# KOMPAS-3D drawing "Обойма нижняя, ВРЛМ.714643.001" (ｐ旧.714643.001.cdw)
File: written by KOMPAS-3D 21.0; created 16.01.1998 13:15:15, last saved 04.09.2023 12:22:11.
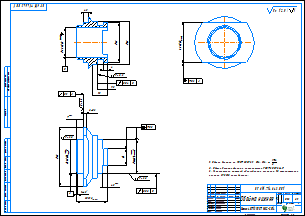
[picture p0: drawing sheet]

Sheet 1: A2, landscape

Document properties: Масса: 0.13304; Литера: О@111~; Знак неуказанной шероховатости: 4; Параметр неуказанной шероховатости: Ra 12,5; Полное имя файла: D:\2023\Чертежи dwg cdw\ВРЛМ.714643.001_.cdw

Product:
- Part/product: Обойма нижняя  | designation ВРЛМ.714643.001
    Материал: Сталь 40Х13 ГОСТ 5632-2014 (density 7650 kg/m3)
    Масса: 0.13304

Title block, sheet 1: Наименование: Обойма нижняя; designation: ВРЛМ.714643.001; Материал: Сталь 40Х13 ГОСТ 5632-2014; Масса: 0,13; Количество листов документа: 1; organisation: ООО "Вириал" / Санкт-Петербург / 2003; cell 10: Т.контр.; Форматы листов документа: A2; stored path: C:\Cadman\Template.sys\template.cdw; Разработал: Соловьева; Проверил: Васильев; Т. контр.: Ковеленов; Подписал: Серов; Н. контр.: Воден; Утвердил: Радциг; Разработал, date: 08.02.2007

Views: Вид 1, Сзади, Проекционный вид 2, Местный разрез 1, Проекционный вид 3
Referenced files in W:\ВРЛМ.714643.001\: ВРЛМ.714643.001.m3d
Referenced files in D:\2023\Чертежи dwg cdw\: ВРЛМ.714643.001.m3d
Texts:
  Ra 6,3
  Ra 3,2
  Ra 12,5
  Ra 12,5 ( )
  ВРЛМ.304421.006.000
  Зам.
  ВРЛМ.09-07
  ВРЛМ.714643.001 Обойма нижняя
Dimensions and other numbers on the sheet: 39,5; 4,5; 39; 42; 4; 9,5; 15; 0,04; 28,5; 33; 58; 30; 1; 16; 7; 2±0,3; 0,1; 0,06; 2:1; 2003; 0,13; 08.02.2007

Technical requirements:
  Общие допуски по ГОСТ 30893.1 : H14, h14,     IT14 2 .
  Общие допуски формы и расположения ГОСТ 30893.2-К.
  Расположение уступов образованных размером 16 относительно
  размера 39,5h12 произвольное.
